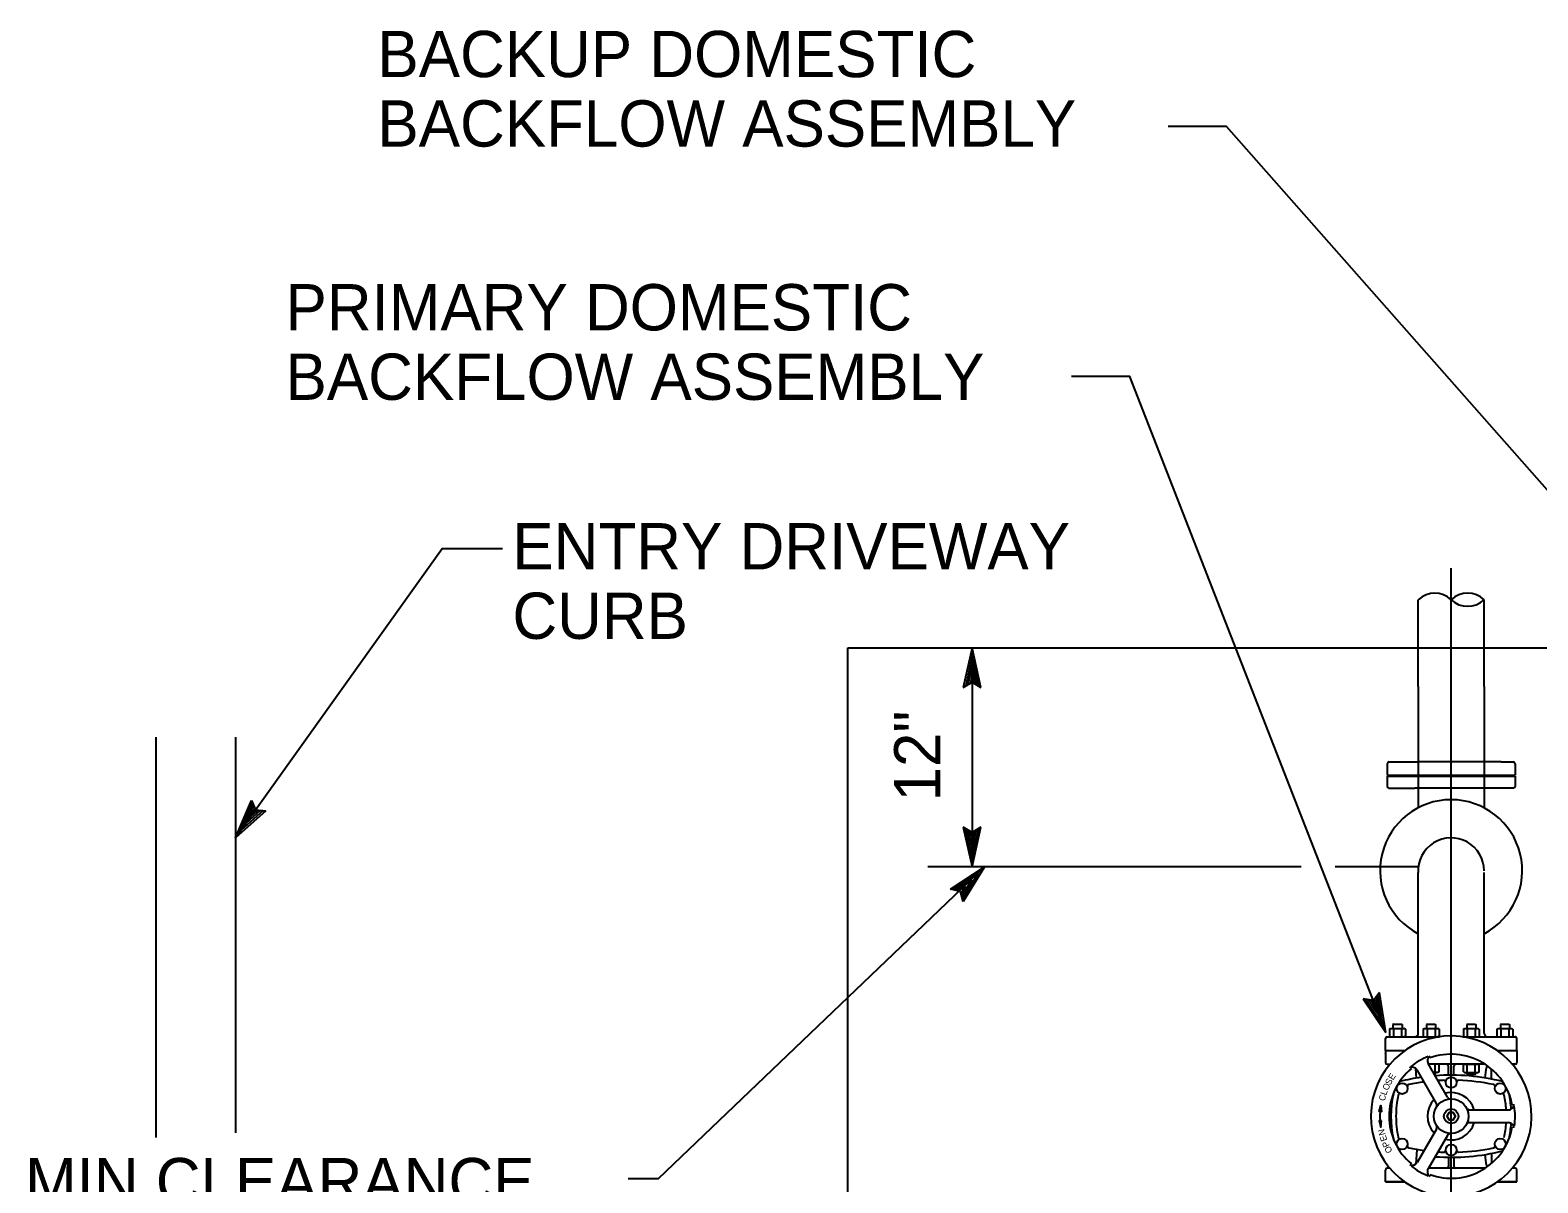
# Model space of a CAD drawing. Extents: x -1680 to 1155, y -802 to 799.
# Drawn here: x 88.5 to 316.4, y -393.8 to -219.5 of the extents above; entities that cross this region are included whole.
import ezdxf

# ---------------------------------------------------------------- set-up
doc = ezdxf.new("R2010")
doc.units = 0
doc.layers.add('Misc CnstDet(22)', color=7, linetype='Continuous')

msp = doc.modelspace()

# ---------------------------------------------------------------- linework, layer by layer
at = {"layer": 'Misc CnstDet(22)'}
for p, q in [((303.25, -548.83), (303.25, -300.88)), ((298.29, -318.73), (298.29, -305.63)), ((308.23, -318.73), (308.23, -305.63)), ((212.09, -312.88), (439.15, -312.88)), ((212.09, -538.09), (212.09, -312.88)), ((230.87, -312.88), (229.54, -318.88)), ((230.87, -314.27), (229.9, -318.65)), ((232.21, -318.88), (230.87, -312.88)), ((230.87, -312.88), (230.87, -312.88)), ((230.87, -312.88), (230.87, -346.02)), ((231.86, -318.66), (230.87, -314.26)), ((230.87, -315.64), (230.25, -318.47)), ((231.5, -318.43), (230.87, -315.64)), ((229.54, -318.88), (230.87, -318.08)), ((229.54, -318.88), (229.54, -318.88)), ((230.88, -317.03), (230.61, -318.23)), ((230.87, -318.08), (232.21, -318.88)), ((231.15, -318.25), (230.88, -317.03)), ((232.21, -318.88), (232.21, -318.88)), ((298.29, -318.73), (298.29, -337.07)), ((308.23, -318.73), (308.23, -337.08)), ((107.55, -326.42), (107.55, -386.93)), ((119.59, -326.42), (119.59, -386.22)), ((293.87, -330.14), (298.27, -330.14)), ((310.79, -330.14), (298.27, -330.14)), ((310.79, -330.14), (312.64, -330.14)), ((293.59, -330.42), (293.59, -332.16)), ((293.59, -332.16), (307.93, -332.16)), ((293.59, -332.29), (293.59, -333.84)), ((293.59, -332.29), (307.64, -332.29)), ((307.64, -332.29), (312.91, -332.29)), ((307.93, -332.16), (312.92, -332.16)), ((312.91, -332.29), (312.91, -333.84)), ((312.92, -330.42), (312.92, -332.16)), ((293.85, -334.1), (297.76, -334.1)), ((308.76, -334.1), (297.76, -334.1)), ((312.66, -334.1), (308.75, -334.1)), ((119.59, -341.65), (121.98, -335.98)), ((120.39, -340.51), (122.13, -336.38)), ((121.19, -339.4), (122.31, -336.73)), ((121.98, -335.98), (121.98, -335.98)), ((121.98, -335.98), (122.6, -337.41)), ((121.99, -338.27), (122.47, -337.13)), ((124.16, -337.53), (119.59, -341.65)), ((123.74, -337.5), (120.39, -340.52)), ((123.31, -337.48), (121.19, -339.4)), ((122.93, -337.43), (121.99, -338.27)), ((122.6, -337.41), (124.16, -337.53)), ((124.16, -337.53), (124.16, -337.53)), ((119.59, -341.65), (119.59, -341.65)), ((230.87, -340.82), (229.53, -340.02)), ((229.53, -340.02), (229.53, -340.02)), ((229.53, -340.02), (230.87, -346.02)), ((229.89, -340.24), (230.87, -344.64)), ((230.25, -340.47), (230.87, -343.26)), ((230.59, -340.65), (230.87, -341.88)), ((230.87, -346.02), (232.2, -340.02)), ((232.2, -340.02), (230.87, -340.82)), ((230.87, -343.26), (231.5, -340.43)), ((230.87, -341.88), (231.14, -340.67)), ((230.88, -344.63), (231.84, -340.26)), ((232.2, -340.02), (232.2, -340.02)), ((280.57, -346.02), (224.16, -346.02)), ((227.6, -349.36), (232.76, -346.02)), ((232.76, -346.02), (229.5, -351.23)), ((230.87, -346.02), (230.87, -346.02)), ((232.76, -346.02), (232.76, -346.02)), ((298.32, -346.02), (285.72, -346.02)), ((228, -349.45), (231.79, -347.01)), ((228.42, -349.54), (230.82, -347.99)), ((230.82, -347.99), (229.29, -350.44)), ((231.79, -347.02), (229.41, -350.81)), ((298.29, -365.03), (298.29, -346.86)), ((308.23, -365.03), (308.23, -346.86)), ((229.12, -349.73), (227.6, -349.36)), ((227.6, -349.36), (227.6, -349.36)), ((228.8, -349.66), (229.85, -348.97)), ((229.5, -351.23), (229.12, -349.73)), ((229.85, -348.97), (229.2, -350.02)), ((229.5, -351.23), (229.5, -351.23)), ((291.5, -366.22), (289.96, -365.96)), ((289.96, -365.96), (289.96, -365.96)), ((289.96, -365.96), (293.39, -371.07)), ((290.37, -366.04), (292.89, -369.78)), ((290.79, -366.12), (292.39, -368.49)), ((291.18, -366.16), (291.88, -367.21)), ((292.45, -364.99), (291.5, -366.22)), ((291.88, -367.21), (291.69, -365.98)), ((292.39, -368.49), (291.94, -365.63)), ((292.89, -369.77), (292.2, -365.34)), ((293.39, -371.07), (292.45, -364.99)), ((292.45, -364.99), (292.45, -364.99)), ((298.29, -371.16), (298.29, -365.03)), ((308.23, -371.16), (308.23, -365.03)), ((293.39, -371.07), (293.39, -371.07)), ((293.95, -370.56), (294.11, -370.47)), ((293.95, -370.56), (293.95, -371.61)), ((294.11, -370.47), (296.18, -370.47)), ((294.52, -369.78), (294.46, -369.84)), ((294.46, -369.84), (294.46, -370.47)), ((294.52, -369.78), (295.77, -369.78)), ((294.55, -370.57), (294.55, -371.61)), ((295.74, -370.57), (295.74, -371.61)), ((295.77, -369.78), (295.84, -369.84)), ((295.84, -369.84), (295.84, -370.47)), ((296.34, -370.56), (296.18, -370.47)), ((296.34, -370.56), (296.34, -371.61)), ((299.03, -370.56), (299.19, -370.47)), ((299.03, -370.56), (299.03, -371.61)), ((299.19, -370.47), (301.26, -370.47)), ((299.6, -369.78), (299.53, -369.84)), ((299.53, -369.84), (299.53, -370.47)), ((299.6, -369.78), (300.85, -369.78)), ((299.63, -370.57), (299.63, -371.61)), ((300.82, -370.57), (300.82, -371.61)), ((300.85, -369.78), (300.91, -369.84)), ((300.91, -369.84), (300.91, -370.47)), ((301.42, -370.56), (301.26, -370.47)), ((301.42, -370.56), (301.42, -371.61)), ((305.1, -370.56), (305.26, -370.47)), ((305.1, -370.56), (305.1, -371.61)), ((305.26, -370.47), (307.33, -370.47)), ((305.68, -369.78), (305.61, -369.84)), ((305.61, -369.84), (305.61, -370.47)), ((305.68, -369.78), (306.92, -369.78)), ((305.7, -370.57), (305.7, -371.61)), ((306.9, -370.57), (306.9, -371.61)), ((306.92, -369.78), (306.99, -369.84)), ((306.99, -369.84), (306.99, -370.47)), ((307.49, -370.56), (307.33, -370.47)), ((307.49, -370.56), (307.49, -371.61)), ((310.18, -370.56), (310.34, -370.47)), ((310.18, -370.56), (310.18, -371.61)), ((310.34, -370.47), (312.41, -370.47)), ((310.75, -369.78), (310.69, -369.84)), ((310.69, -369.84), (310.69, -370.47)), ((310.75, -369.78), (312, -369.78)), ((310.78, -370.57), (310.78, -371.61)), ((311.97, -370.57), (311.97, -371.61)), ((312, -369.78), (312.07, -369.84)), ((312.07, -369.84), (312.07, -370.47)), ((312.57, -370.56), (312.41, -370.47)), ((312.57, -370.56), (312.57, -371.61)), ((293.33, -373.78), (293.33, -371.98)), ((293.6, -371.71), (301.44, -371.71)), ((293.95, -371.61), (294.11, -371.71)), ((294.11, -371.71), (296.18, -371.71)), ((296.34, -371.61), (296.18, -371.71)), ((299.03, -371.61), (299.19, -371.71)), ((299.19, -371.71), (301.26, -371.71)), ((301.42, -371.61), (301.26, -371.71)), ((305.09, -371.71), (312.92, -371.71)), ((305.1, -371.61), (305.26, -371.71)), ((305.26, -371.71), (307.33, -371.71)), ((307.49, -371.61), (307.33, -371.71)), ((310.18, -371.61), (310.34, -371.71)), ((310.34, -371.71), (312.41, -371.71)), ((312.57, -371.61), (312.41, -371.71)), ((313.19, -373.78), (313.19, -371.98)), ((293.33, -373.78), (293.33, -375.57)), ((293.33, -373.78), (296.28, -373.78)), ((293.33, -373.78), (296.28, -373.78)), ((293.33, -374.29), (293.33, -375.57)), ((293.6, -375.85), (294.01, -375.85)), ((293.95, -375.85), (293.95, -375.92)), ((302.7, -380.81), (299.77, -375.74)), ((308.38, -375.85), (299.84, -375.85)), ((301.26, -375.85), (299.84, -375.85)), ((301.42, -375.94), (301.26, -375.85)), ((305.1, -375.94), (305.26, -375.85)), ((305.26, -375.85), (307.33, -375.85)), ((307.49, -375.94), (307.33, -375.85)), ((310.24, -373.78), (313.19, -373.78)), ((310.24, -373.78), (313.19, -373.78)), ((312.92, -375.85), (312.51, -375.85)), ((312.57, -375.85), (312.57, -375.92)), ((313.19, -373.78), (313.19, -375.57)), ((298.03, -377.94), (297.93, -376.49)), ((301.03, -381.78), (298.1, -376.71)), ((301.26, -377.08), (300.55, -377.08)), ((300.85, -377.36), (300.71, -377.36)), ((300.82, -376.99), (300.82, -375.94)), ((300.85, -377.36), (300.91, -377.29)), ((300.91, -377.29), (300.91, -377.08)), ((301.42, -376.99), (301.26, -377.08)), ((301.42, -376.99), (301.42, -375.94)), ((302.85, -377.5), (302.85, -376.12)), ((303.67, -377.5), (303.67, -376.12)), ((305.1, -376.99), (305.1, -375.94)), ((305.1, -376.99), (305.26, -377.08)), ((305.26, -377.08), (307.33, -377.08)), ((305.61, -377.29), (305.61, -377.08)), ((305.67, -377.36), (305.61, -377.29)), ((305.67, -377.36), (306.92, -377.36)), ((305.7, -376.99), (305.7, -375.94)), ((306.9, -376.99), (306.9, -375.94)), ((306.92, -377.36), (306.99, -377.29)), ((306.99, -377.29), (306.99, -377.08)), ((307.49, -376.99), (307.33, -377.08)), ((307.49, -376.99), (307.49, -375.94)), ((309.33, -378.09), (309.33, -376.56)), ((306.05, -382.74), (311.91, -382.74)), ((306.05, -384.68), (311.91, -384.68)), ((301.03, -385.64), (298.1, -390.71)), ((302.7, -386.61), (299.77, -391.68)), ((298.08, -388.72), (297.93, -390.93)), ((309.33, -389.33), (309.33, -390.86)), ((294.01, -391.57), (293.6, -391.57)), ((308.38, -391.57), (299.84, -391.57)), ((302.85, -389.91), (302.85, -391.3)), ((303.67, -389.91), (303.67, -391.3)), ((312.92, -391.57), (312.51, -391.57)), ((293.33, -393.64), (293.33, -391.85)), ((296.28, -393.64), (293.33, -393.64)), ((293.33, -393.64), (296.28, -393.64)), ((313.19, -393.64), (310.24, -393.64)), ((310.24, -393.64), (313.19, -393.64)), ((313.19, -393.64), (313.19, -391.85))]:
    msp.add_line(p, q, dxfattribs=at)
for points in [[(390.45, -371.41), (269.3, -234.08), (260.5, -234.08)], [(293.39, -371.07), (254.7, -271.89), (245.9, -271.89)], [(119.59, -341.65), (150.79, -297.87), (159.91, -297.87)], [(232.76, -346.02), (183.44, -393.18), (178.92, -393.18)]]:
    msp.add_lwpolyline(points, dxfattribs=at)
for points in [[(292.71, -383.02), (292.4, -383), (292.62, -382.08)], [(292.71, -384.4), (292.4, -384.42), (292.62, -385.34)], [(302.94, -383.16), (302.62, -383.71), (302.94, -384.26), (303.58, -384.26), (303.9, -383.71), (303.58, -383.16)]]:
    msp.add_lwpolyline(points, close=True, dxfattribs=at)
for centre, radius in [((303.26, -378.61), 0.828), ((295.85, -379.52), 0.828), ((310.67, -379.52), 0.828), ((303.26, -383.71), 2.62), ((303.26, -383.71), 1.1), ((295.85, -387.9), 0.828), ((310.67, -387.9), 0.828), ((303.26, -388.81), 0.828)]:
    msp.add_circle(centre, radius, dxfattribs=at)
for centre, radius, start, end in [((300.78, -308.25), 3.61, 46.4429, 133.4774), ((305.75, -308.25), 3.61, 46.5406, 133.539), ((305.74, -303.03), 3.6, 226.4033, 313.6763), ((293.87, -330.42), 0.279, 90, 180), ((312.64, -330.42), 0.279, 0, 90), ((293.85, -333.84), 0.258, 180, 270), ((312.66, -333.84), 0.258, 270, 0), ((303.25, -346.6), 10.74, 297.5711, 242.4959), ((303.25, -346.6), 4.97, 0.0006, 183.0872), ((297.74, -371.16), 0.552, 270, 0), ((308.78, -371.16), 0.552, 180, 270), ((303.26, -383.71), 12.14, 89.4109, 89.3632), ((293.6, -371.98), 0.276, 90, 180), ((312.92, -371.98), 0.276, 39.9587, 90), ((312.92, -371.98), 0.276, 0, 90), ((293.05, -374.29), 0.276, 0, 11.7683), ((293.6, -375.57), 0.276, 180, 270), ((303.26, -383.71), 9.66, 111.1733, 129.046), ((300.49, -375.33), 0.828, 121.7915, 210), ((303.26, -383.71), 9.38, 9.8969, 110.1031), ((302.57, -376.12), 0.276, 0, 90), ((303.95, -376.12), 0.276, 90, 180), ((312.92, -375.57), 0.276, 270, 0), ((303.26, -383.71), 9.38, 129.8969, 230.1031), ((303.26, -409.09), 31.59, 98.2117, 104.2666), ((297.38, -377.12), 0.828, 30, 121.3135), ((303.26, -409.09), 31.59, 75.7334, 94.3855), ((319.04, -378.99), 10.77, 165.4239, 174.2397), ((309.52, -376.56), 0.95, 148.9584, 162.6862), ((310.31, -383.71), 16.15, 167.8489, 192.1511), ((295.52, -380.57), 0.276, 72.3405, 168.0139), ((296.91, -379.2), 0.276, 101.9908, 196.6074), ((303.26, -409.09), 30.83, 97.6469, 101.9908), ((303.26, -409.09), 30.83, 92.0678, 93.7076), ((302.16, -378.56), 0.276, 357.4512, 92.0678), ((303.26, -383.71), 3.59, 15.6185, 104.3815), ((304.36, -378.56), 0.276, 87.9322, 182.5489), ((303.26, -409.09), 30.83, 78.0092, 87.9322), ((309.61, -379.2), 0.276, 343.3926, 78.0092), ((311, -380.57), 0.276, 11.9861, 107.6595), ((296.21, -383.71), 16.15, 3.9315, 12.1511), ((303.26, -383.71), 10.76, 173.2861, 186.7139), ((310.31, -383.71), 15.39, 168.0139, 180), ((303.26, -383.71), 3.59, 135.6185, 224.3815), ((300.55, -382.05), 0.552, 328.5719, 30), ((303.18, -380.54), 0.552, 210, 271.4281), ((306.05, -382.19), 0.552, 208.5719, 270), ((296.21, -383.71), 15.39, 3.5967, 11.9861), ((311.91, -381.92), 0.828, 270, 1.3135), ((303.26, -383.71), 9.66, 351.1733, 9.046), ((310.31, -383.71), 15.39, 180, 191.9861), ((303.26, -383.71), 3.59, 255.6185, 344.3815), ((306.05, -385.23), 0.552, 90, 151.4281), ((296.21, -383.71), 15.39, 348.0139, 356.4033), ((311.91, -385.5), 0.828, 1.7915, 90), ((296.21, -383.71), 16.15, 347.8489, 356.0685), ((295.52, -386.85), 0.276, 191.9861, 287.6595), ((303.26, -383.71), 9.38, 249.8969, 350.1031), ((300.55, -385.36), 0.552, 330, 31.4281), ((303.18, -386.88), 0.552, 88.5719, 150), ((296.91, -388.22), 0.276, 163.3926, 258.0092), ((303.26, -358.33), 30.83, 258.0092, 262.3531), ((303.26, -358.33), 31.59, 265.6145, 284.2666), ((303.26, -358.33), 30.83, 266.2924, 267.9322), ((302.16, -388.86), 0.276, 267.9322, 2.5489), ((304.36, -388.86), 0.276, 177.4512, 272.0678), ((303.26, -358.33), 30.83, 272.0678, 281.9908), ((319.04, -388.43), 10.77, 185.7603, 194.5761), ((309.61, -388.22), 0.276, 281.9908, 16.6074), ((293.6, -391.85), 0.276, 90, 180), ((297.38, -390.3), 0.828, 241.7915, 330), ((303.26, -383.71), 9.66, 231.1733, 249.046), ((300.49, -392.09), 0.828, 150, 241.3135), ((302.57, -391.3), 0.276, 270, 0), ((303.95, -391.3), 0.276, 180, 270), ((309.52, -390.86), 0.95, 197.3138, 211.0416), ((312.92, -391.85), 0.276, 0, 90)]:
    msp.add_arc(centre, radius, start, end, dxfattribs=at)

# ---------------------------------------------------------------- texts
for s, p in [('BACKUP DOMESTIC', (141.01, -226.64)), ('BACKFLOW ASSEMBLY', (141.01, -237.14)), ('PRIMARY DOMESTIC', (127.13, -264.92)), ('BACKFLOW ASSEMBLY', (127.13, -275.42)), ('ENTRY DRIVEWAY', (161.41, -301.05)), ('CURB', (161.41, -311.55))]:
    msp.add_text(s, height=7, dxfattribs=at).set_placement(p)
for s, height, rotation, p in [('12"', 7, 90, (226.09, -336.13)), ('S', 0.966, 62.0107, (294.07, -379.08)), ('E', 0.966, 57.3232, (294.48, -378.33)), ('C', 0.966, 76.0732, (293.22, -381.47)), ('L', 0.966, 71.3857, (293.45, -380.61)), ('O', 0.966, 66.6982, (293.71, -379.89)), ('N', 0.966, 104.3391, (293.35, -386.47)), ('E', 0.966, 109.3391, (293.63, -387.31)), ('P', 0.966, 114.3391, (293.99, -388.15)), ('O', 0.966, 119.3391, (294.43, -388.97)), ('MIN CLEARANCE', 7, 360, (87.77, -397.02))]:
    msp.add_text(s, height=height, rotation=rotation, dxfattribs=at).set_placement(p)

doc.saveas('drawing.dxf')
